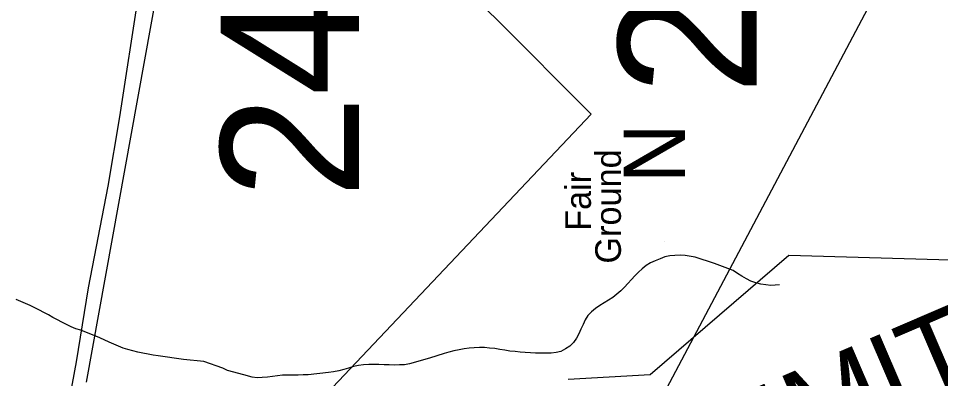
# Model space of a CAD drawing. Extents: x 1372027 to 1374286, y 553832 to 556743.
# Drawn here: x 1373235 to 1373297, y 554175.8 to 554200 of the extents above; entities that cross this region are included whole.
import ezdxf

# ---------------------------------------------------------------- set-up
doc = ezdxf.new("R2010")
doc.units = 0
for name, color, linetype in [('Old_Level_12', 7, 'Continuous'), ('Prop DGN Element Guardrail', 7, 'Continuous'), ('Prop Dimension', 7, 'Continuous'), ('Prop Dimension Text', 7, 'Continuous'), ('Sheet Clip Boundary CELL', 7, 'Continuous'), ('Sheet North Arrow Point CELL', 7, 'Continuous'), ('Sheet Sticker Preliminary CELL', 7, 'Continuous')]:
    doc.layers.add(name, color=color, linetype=linetype)

msp = doc.modelspace()

# ---------------------------------------------------------------- linework, layer by layer
at = {"layer": 'Prop DGN Element Guardrail'}
for points in [[(1373243.386, 554203.709), (1373243.107, 554201.727), (1373241.82, 554193.415), (1373241.036, 554188.767), (1373239.731, 554181.914), (1373238.913, 554176.94), (1373237.716, 554170.377), (1373237.257, 554165.388), (1373236.405, 554161.785)], [(1373239.621, 554175.593), (1373244.383, 554201.972), (1373244.679, 554203.581)]]:
    msp.add_lwpolyline(points, dxfattribs=at)
at = {"layer": 'Prop Dimension'}
msp.add_line((1373297.698, 554211.343), (1373265.721, 554150.896), dxfattribs=at)
at = {"layer": 'Prop Dimension Text'}
for p, q in [((1373267.119, 554200.002), (1373258.921, 554207.908)), ((1373273.513, 554193.601), (1373267.119, 554200.002)), ((1373236.262, 554154.246), (1373273.513, 554193.601)), ((1373286.769, 554184.105), (1373277.466, 554176.072)), ((1373305.647, 554183.527), (1373286.769, 554184.105)), ((1373277.466, 554176.072), (1373271.954, 554175.772))]:
    msp.add_line(p, q, dxfattribs=at)
at = {"layer": 'Sheet North Arrow Point CELL'}
msp.add_line((1373278.453, 554185.051), (1373278.453, 554185.051), dxfattribs=at)
at = {"layer": 'Sheet Sticker Preliminary CELL'}
for points in [[(1373286.144, 554182.135), (1373285.575, 554182.087), (1373285.234, 554182.115), (1373284.892, 554182.176), (1373284.554, 554182.257), (1373284.231, 554182.371), (1373283.925, 554182.524), (1373283.63, 554182.705), (1373283.341, 554182.897), (1373283.048, 554183.082), (1373281.782, 554183.553), (1373280.489, 554183.991), (1373279.823, 554184.096), (1373279.477, 554184.109), (1373279.13, 554184.105), (1373278.79, 554184.064), (1373278.449, 554183.999), (1373278.127, 554183.881), (1373277.805, 554183.745), (1373277.491, 554183.599), (1373277.197, 554183.422), (1373276.932, 554183.207), (1373276.682, 554182.972), (1373276.441, 554182.727), (1373276.204, 554182.473), (1373275.97, 554182.216), (1373275.732, 554181.964), (1373275.486, 554181.721), (1373275.231, 554181.493), (1373274.958, 554181.284), (1373274.671, 554181.093), (1373274.378, 554180.91), (1373274.085, 554180.727), (1373273.799, 554180.533), (1373273.525, 554180.32), (1373273.284, 554180.072), (1373273.109, 554179.779), (1373272.959, 554179.469), (1373272.819, 554179.153), (1373272.676, 554178.836), (1373272.516, 554178.533), (1373272.308, 554178.257), (1373272.079, 554177.996), (1373271.785, 554177.816), (1373271.475, 554177.654), (1373271.147, 554177.568), (1373270.807, 554177.534), (1373270.461, 554177.525), (1373270.112, 554177.529), (1373269.767, 554177.54), (1373269.422, 554177.553), (1373269.079, 554177.577), (1373268.734, 554177.605), (1373268.392, 554177.639), (1373268.05, 554177.676), (1373267.709, 554177.727), (1373267.368, 554177.788), (1373267.028, 554177.841), (1373266.686, 554177.878), (1373266.341, 554177.904), (1373265.996, 554177.915), (1373265.652, 554177.9), (1373265.31, 554177.863), (1373264.969, 554177.813), (1373264.629, 554177.755), (1373264.289, 554177.686), (1373263.954, 554177.609), (1373263.627, 554177.501), (1373262.641, 554177.204), (1373261.314, 554176.819), (1373260.977, 554176.758), (1373260.636, 554176.737), (1373260.292, 554176.73), (1373259.947, 554176.737), (1373259.6, 554176.75), (1373259.253, 554176.763), (1373258.907, 554176.771), (1373258.562, 554176.771), (1373258.22, 554176.756), (1373257.881, 554176.713), (1373257.547, 554176.631), (1373257.216, 554176.53), (1373256.884, 554176.429), (1373256.548, 554176.345), (1373256.209, 554176.28), (1373255.868, 554176.233), (1373254.508, 554176.078), (1373254.165, 554176.065), (1373253.819, 554176.061), (1373253.475, 554176.061), (1373253.129, 554176.059), (1373252.785, 554176.044), (1373252.441, 554176.011), (1373252.099, 554175.97), (1373251.757, 554175.927), (1373251.414, 554175.891), (1373251.071, 554175.876), (1373250.729, 554175.927), (1373250.181, 554176.072)], [(1373250.181, 554176.072), (1373249.083, 554176.36), (1373248.774, 554176.517), (1373247.492, 554176.965), (1373246.124, 554177.105), (1373244.421, 554177.346), (1373244.081, 554177.407), (1373243.742, 554177.469), (1373243.404, 554177.538), (1373243.066, 554177.609), (1373242.73, 554177.689), (1373242.397, 554177.775), (1373242.068, 554177.874), (1373241.123, 554178.281), (1373240.507, 554178.567), (1373239.226, 554179.069), (1373238.898, 554179.172), (1373238.58, 554179.305), (1373238.27, 554179.454), (1373237.963, 554179.609), (1373237.658, 554179.771), (1373237.355, 554179.934), (1373237.052, 554180.1), (1373236.749, 554180.264), (1373236.443, 554180.425), (1373236.136, 554180.58), (1373235.825, 554180.729), (1373235.512, 554180.873), (1373235.196, 554181.013), (1373234.879, 554181.149)]]:
    msp.add_lwpolyline(points, dxfattribs=at)

# ---------------------------------------------------------------- texts
at = {"layer": 'Old_Level_12'}
for s, p in [('2439', (1373284.626, 554194.902)), ('2481', (1373257.912, 554187.935))]:
    msp.add_text(s, height=9.3012, rotation=90, dxfattribs=at).set_placement(p)
at = {"layer": 'Sheet Clip Boundary CELL'}
msp.add_text('LIMITS', height=5.67, rotation=23.26575, dxfattribs=at).set_placement((1373282.21, 554168.045))
at = {"layer": 'Sheet North Arrow Point CELL'}
for s, height, p in [('N', 4.134, (1373279.812, 554188.961)), ('Ground', 1.7224, (1373275.501, 554183.551)), ('Fair', 1.7224, (1373273.488, 554185.754))]:
    msp.add_text(s, height=height, rotation=90.00002, dxfattribs=at).set_placement(p)

doc.saveas('drawing.dxf')
